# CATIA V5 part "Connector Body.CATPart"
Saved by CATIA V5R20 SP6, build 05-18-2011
Part number: Connector Body
Bounding box of the stored display mesh (mm): x -10 to 10, y -57 to 0, z 0 to 7
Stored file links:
  E:\#03 University\#02 영남 이공대\#01 2021\#02 여름 방학\#01 Documents\K-Move Page02 ASD02\Connector Body.CATPart
  C:\Program Files\Dassault Systemes\B20\win_b64\reffiles\standard\MetricThickPitch.txt

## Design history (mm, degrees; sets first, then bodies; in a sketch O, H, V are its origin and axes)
Set1 "Reference Data"
  Point1 "Center Point": (0, 0, 0)
Body1 (main body)
  Body2
    Sketch1 on xy-plane, origin (0, 0, 0), H (0, 1, 0), V (-1, 0, 0)
      arc A1 centre (0, 0) radius 4 from (0, 4) to (0, -4) ccw
      circle A2 centre (-52, 0) radius 2
      point P1 (-52, 0)
      point P2 (0, 4)
      line L1 (0, 4) -> (0, 10)
      point P3 (0, 10)
      line L2 (0, 10) -> (-6, 10)
      point P4 (-6, 10)
      line L3 (-6, 10) -> (-6, 5)
      point P5 (-6, 5)
      line L4 (-6, 5) -> (-52, 5)
      point P6 (-6, -5)
      point P7 (-6, -10)
      point P8 (0, -10)
      line L5 (-6, -5) -> (-52, -5)
      line L6 (-6, -10) -> (-6, -5)
      line L7 (0, -10) -> (-6, -10)
      line L8 (0, -4) -> (0, -10)
      arc A3 centre (-52, 0) radius 5 from (-52, 5) to (-52, -5) ccw
      distance L2 L7 = 20
      radius A1 = 4
      radius A2 = 2
      distance L4 L5 = 10
      distance P1 V = 52
      distance L8 L6 = 6
      coincidence: P1 H, P2 A1, P2 V, P2 L1
      vertical: L1 V, L3 V
      horizontal: L2 H, L4 H
      symmetry: P5 P6 H, P4 P7 H, P3 P8 H, L4 L5 H, L3 L6 H, L2 L7 H, L1 L8 H
      tangency: A3 L4
    Pad1: profile Sketch1, direction (0, 0, 1), length 7
    Sketch2 on face of Pad1 from Sketch1.L1, origin (-7.2626, 0, 3.8064), H (1, 0, 0), V (0, 0, -1)
      point P1 (-0.2374, 0.3064)
      reference intersected line E1 through (7.2626, 0) direction (0, 1) from yz-plane
      reference intersected line E2 through (0, 3.8064) direction (1, 0) from xy-plane
      distance P1 E1 = 7.5
      distance P1 E2 = 3.5
    Hole1: placed by Sketch2, at (-7.5, 0, 3.5) direction (0, -1, 0), diameter 2.459, depth 10, threaded "M3", thread diameter 3, thread depth 10, pitch 0.5
    Mirror1: of Hole1, about yz-plane
  Assemble1: tool Body2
